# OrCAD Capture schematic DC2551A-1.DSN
size Custom; note: CONFIGURABLE PRECISION AMPLIFIER
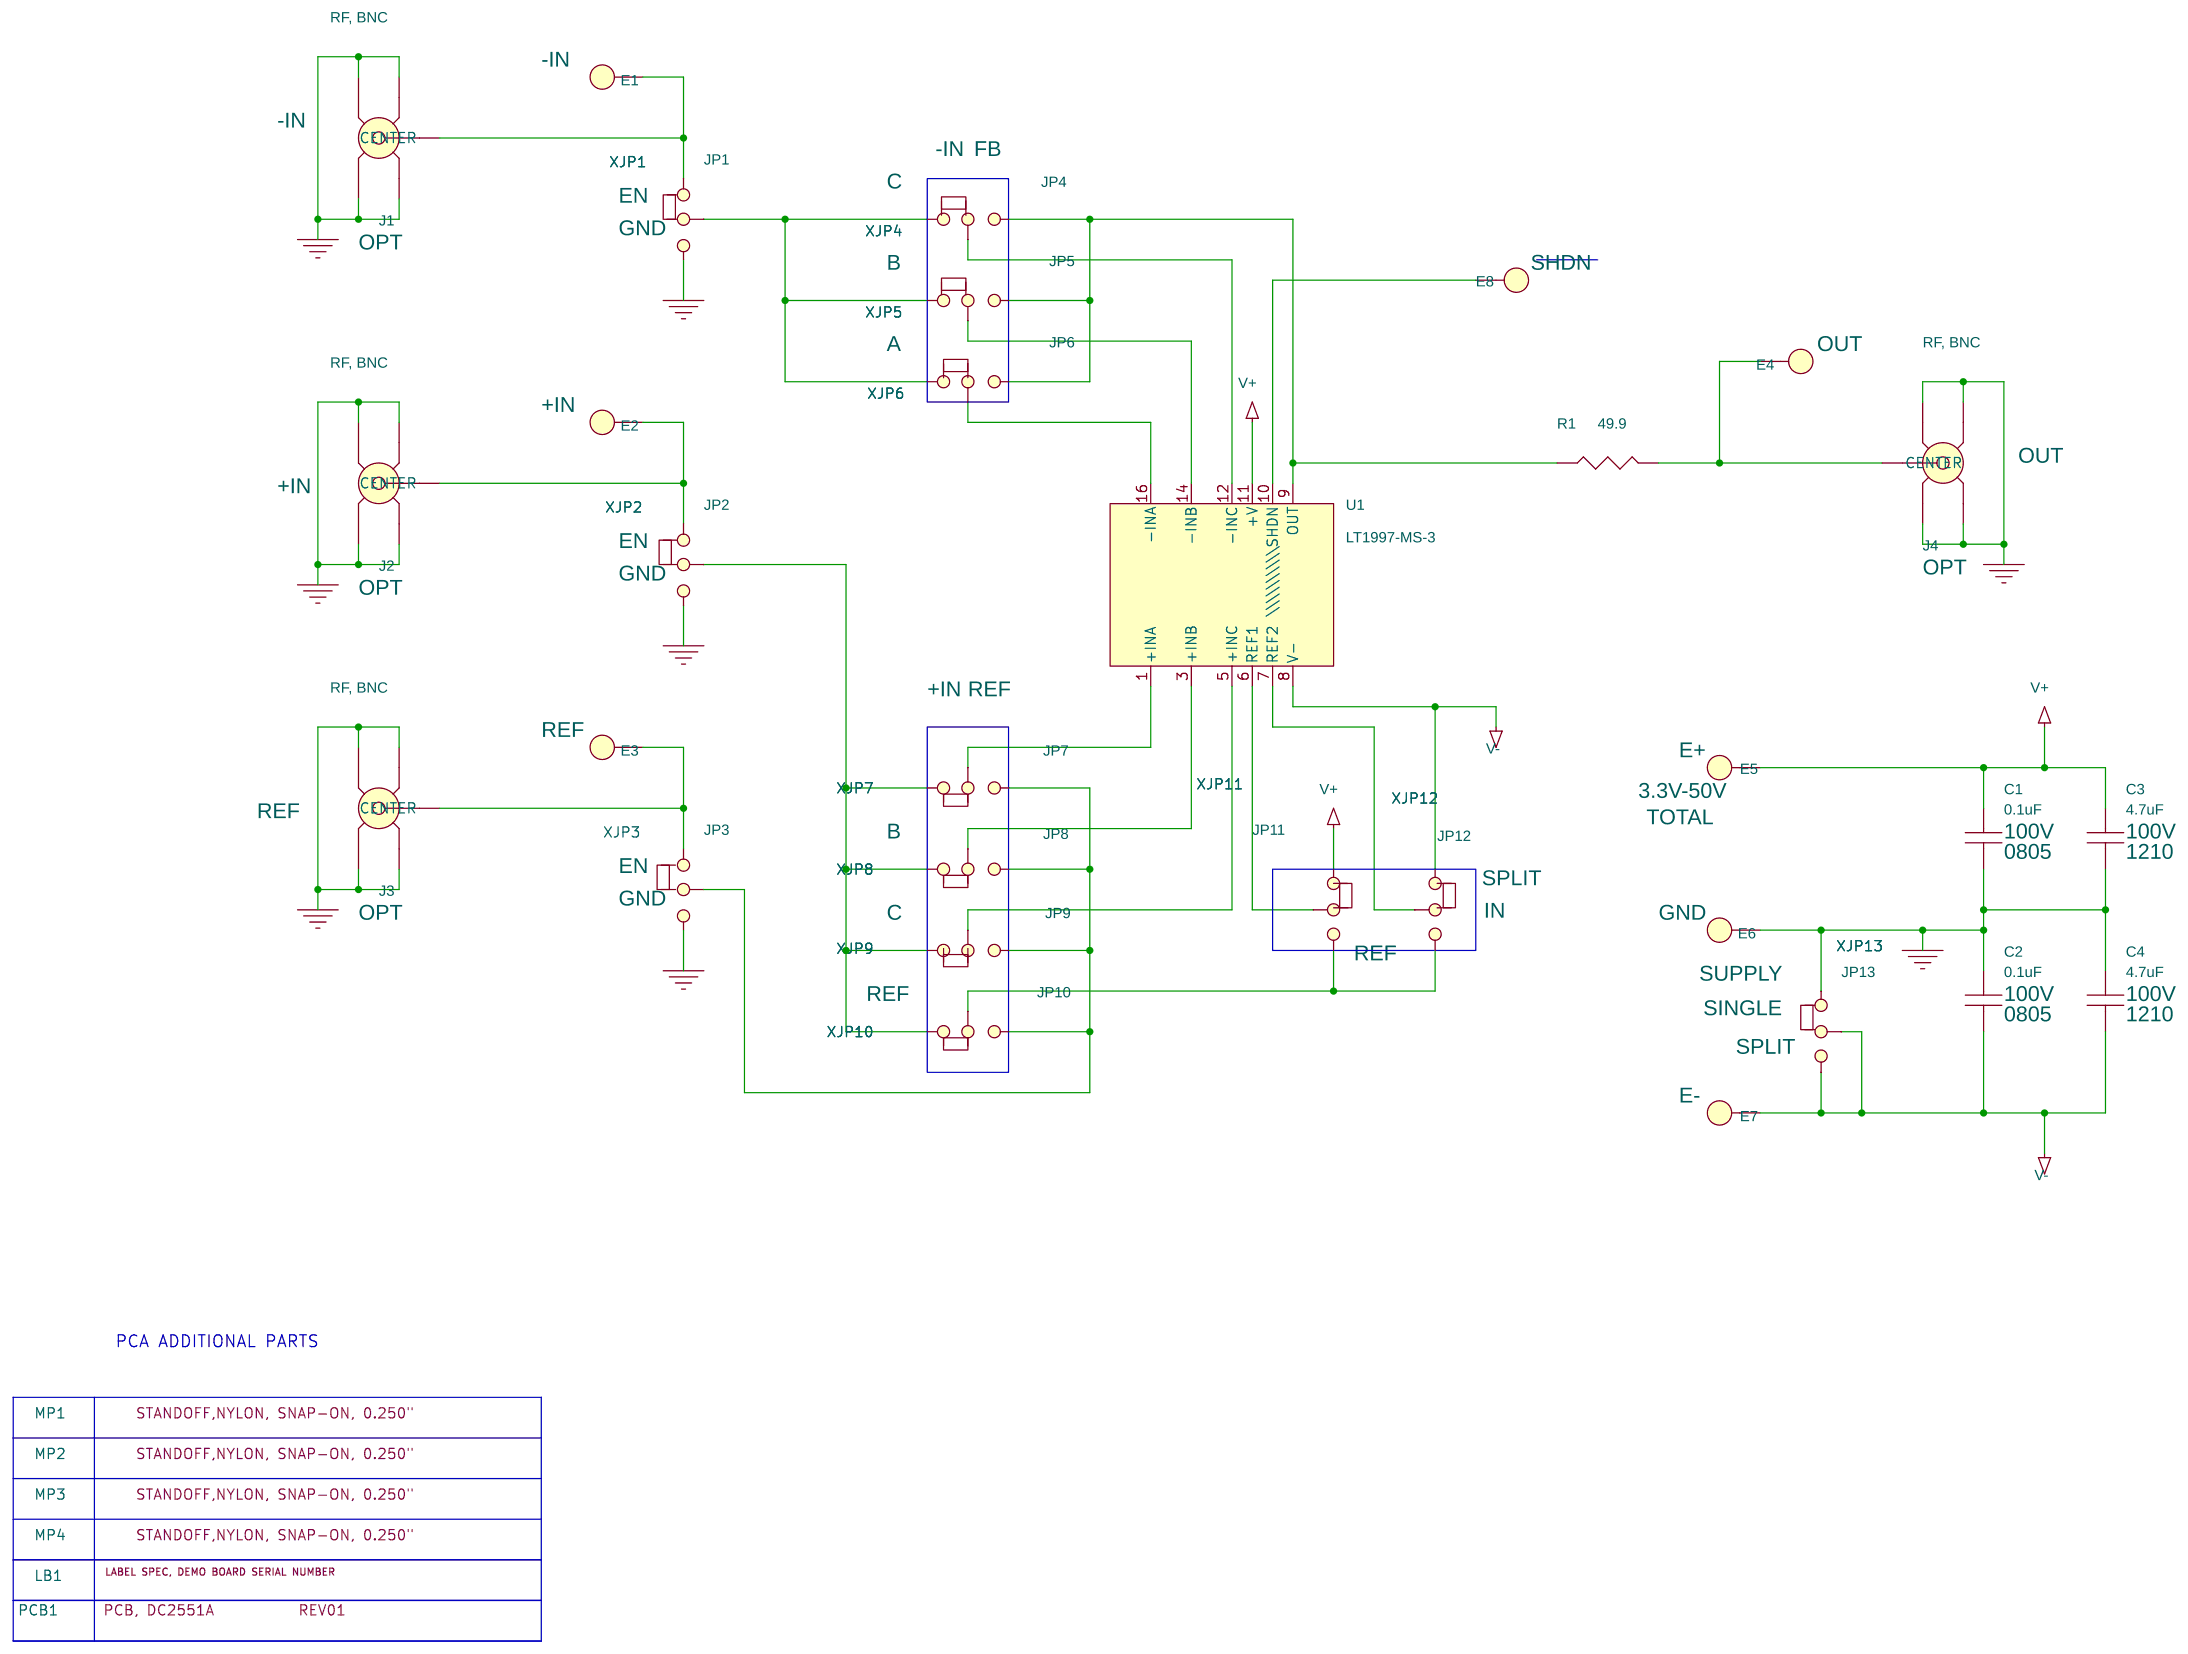
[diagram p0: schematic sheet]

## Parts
C1  0.1uF  [CC0805N]
C2  0.1uF  [CC0805N]
C3  4.7uF  [CC1210N]
C4  4.7uF  [CC1210N]
E1  TEST POINT  [MILLMAX2308]
E2  TEST POINT  [MILLMAX2308]
E3  TEST POINT  [MILLMAX2308]
E4  TEST POINT  [MILLMAX2308]
E5  TEST POINT  [MILLMAX2308]
E6  TEST POINT  [MILLMAX2308]
E7  TEST POINT  [MILLMAX2308]
E8  TEST POINT  [MILLMAX2308]
J1  RF, BNC  [CONNEX-112404]
J2  RF, BNC  [CONNEX-112404]
J3  RF, BNC  [CONNEX-112404]
J4  RF, BNC  [CONNEX-112404]
JP1  HDR.  [HD1X3-079]
JP2  HDR.  [HD1X3-079]
JP3  HDR.  [HD1X3-079]
JP4  HDR.  [HD1X3-079]
JP5  HDR.  [HD1X3-079]
JP6  HDR.  [HD1X3-079]
JP7  HDR.  [HD1X3-079]
JP8  HDR.  [HD1X3-079]
JP9  HDR.  [HD1X3-079]
JP10  HDR.  [HD1X3-079]
JP11  HDR.  [HD1X3-079]
JP12  HDR.  [HD1X3-079]
JP13  HDR.  [HD1X3-079]
LB1  LABEL  [895-0154_REV01]
MP1  STANDOFF  [MTG-8831]
MP2  STANDOFF  [MTG-8831]
MP3  STANDOFF  [MTG-8831]
MP4  STANDOFF  [MTG-8831]
PCB1  PCB, DC2551A
R1  49.9  [CR0402N]
U1  LT1997-MS-3  [LTC-MS-16-1847]
XJP1  SHUNT
XJP2  SHUNT
XJP3  SHUNT
XJP4  SHUNT
XJP5  SHUNT
XJP6  SHUNT
XJP7  SHUNT
XJP8  SHUNT
XJP9  SHUNT
XJP10  SHUNT
XJP11  SHUNT
XJP12  SHUNT
XJP13  SHUNT

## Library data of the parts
C1 C2 = CAP: CAP.,0.1uF,X7R,100V,10%,0805,Automotive; CLASS: DISCRETE; Dielectric Type: X7R; FPLIST: CC0805N,CC0805L,CC0805M; Manufacturer: MURATA; Manufacturer PN: GCM21BR72A104KA37L; PART_NUMBER: 150-3339; Package Size: 0805; Rated Voltage: 100V; Tolerance: 10%; UserField01: Automotive
C3 C4 = CAP: CAP.,4.7uF,X7S,100V,10%,1210,Automotive; CLASS: DISCRETE; Dielectric Type: X7S; FPLIST: CC1210N,CC1210L,CC1210M; Manufacturer: TDK; Manufacturer PN: CGA6M3X7S2A475K200AB; PART_NUMBER: 150-3376; Package Size: 1210; Rated Voltage: 100V; Tolerance: 10%; UserField01: Automotive
E1 = TEST_POINT_.156_MILL-MAX_2308: TEST POINT,TURRET,0.064",MTG. HOLE; 1: -IN; CLASS: IO; Manufacturer: MILL-MAX; Manufacturer PN: 2308-2-00-80-00-00-07-0; PART_NUMBER: 260-0004
E2 = TEST_POINT_.156_MILL-MAX_2308: TEST POINT,TURRET,0.064",MTG. HOLE; 1: +IN; CLASS: IO; Manufacturer: MILL-MAX; Manufacturer PN: 2308-2-00-80-00-00-07-0; PART_NUMBER: 260-0004
E3 = TEST_POINT_.156_MILL-MAX_2308: TEST POINT,TURRET,0.064",MTG. HOLE; 1: REF; CLASS: IO; Manufacturer: MILL-MAX; Manufacturer PN: 2308-2-00-80-00-00-07-0; PART_NUMBER: 260-0004
E4 = TEST_POINT_.156_MILL-MAX_2308: TEST POINT,TURRET,0.064",MTG. HOLE; 1: OUT; CLASS: IO; Manufacturer: MILL-MAX; Manufacturer PN: 2308-2-00-80-00-00-07-0; PART_NUMBER: 260-0004
E5 = TEST_POINT_.156_MILL-MAX_2308: TEST POINT,TURRET,0.064",MTG. HOLE; 1: E+; 2: 3.3V-50V; 3: TOTAL; CLASS: IO; Manufacturer: MILL-MAX; Manufacturer PN: 2308-2-00-80-00-00-07-0; PART_NUMBER: 260-0004
E6 = TEST_POINT_.156_MILL-MAX_2308: TEST POINT,TURRET,0.064",MTG. HOLE; 1: GND; CLASS: IO; Manufacturer: MILL-MAX; Manufacturer PN: 2308-2-00-80-00-00-07-0; PART_NUMBER: 260-0004
E7 = TEST_POINT_.156_MILL-MAX_2308: TEST POINT,TURRET,0.064",MTG. HOLE; 1: E-; CLASS: IO; Manufacturer: MILL-MAX; Manufacturer PN: 2308-2-00-80-00-00-07-0; PART_NUMBER: 260-0004
E8 = TEST_POINT_.156_MILL-MAX_2308: TEST POINT,TURRET,0.064",MTG. HOLE; 1: SHDN; CLASS: IO; Manufacturer: MILL-MAX; Manufacturer PN: 2308-2-00-80-00-00-07-0; PART_NUMBER: 260-0004
J1 = BNC_50_OHM_112404: CONN.,RF, BNC,RCPT,THT, STRT,5-PIN; 1: -IN; BOM Notes: OPT; CLASS: IO; Manufacturer: AMPHENOL CONNEX; Manufacturer PN: 112404; PART_NUMBER: 250-0427
J2 = BNC_50_OHM_112404: CONN.,RF, BNC,RCPT,THT, STRT,5-PIN; 1: +IN; BOM Notes: OPT; CLASS: IO; Manufacturer: AMPHENOL CONNEX; Manufacturer PN: 112404; PART_NUMBER: 250-0427
J3 = BNC_50_OHM_112404: CONN.,RF, BNC,RCPT,THT, STRT,5-PIN; 1: REF; BOM Notes: OPT; CLASS: IO; Manufacturer: AMPHENOL CONNEX; Manufacturer PN: 112404; PART_NUMBER: 250-0427
J4 = BNC_50_OHM_112404: CONN.,RF, BNC,RCPT,THT, STRT,5-PIN; 1: OUT; BOM Notes: OPT; CLASS: IO; Manufacturer: AMPHENOL CONNEX; Manufacturer PN: 112404; PART_NUMBER: 250-0427
JP1-JP3 = 3_PIN_HEADER_.079_SINGLE_ROW: CONN.,HDR.,MALE,1X3,2mm,THT, STRT; 1: EN; 2: GND; CLASS: IO; Manufacturer: SULLINS CONNECTOR SOLUTIONS; Manufacturer PN: NRPN031PAEN-RC; PART_NUMBER: 250-0418
JP4 = 3_PIN_HEADER_.079_SINGLE_ROW: CONN.,HDR.,MALE,1X3,2mm,THT, STRT; 1: -IN; 2: FB; 3: C; CLASS: IO; Manufacturer: SULLINS CONNECTOR SOLUTIONS; Manufacturer PN: NRPN031PAEN-RC; PART_NUMBER: 250-0418
JP5 JP8 = 3_PIN_HEADER_.079_SINGLE_ROW: CONN.,HDR.,MALE,1X3,2mm,THT, STRT; 1: B; CLASS: IO; Manufacturer: SULLINS CONNECTOR SOLUTIONS; Manufacturer PN: NRPN031PAEN-RC; PART_NUMBER: 250-0418
JP6 = 3_PIN_HEADER_.079_SINGLE_ROW: CONN.,HDR.,MALE,1X3,2mm,THT, STRT; 1: A; CLASS: IO; Manufacturer: SULLINS CONNECTOR SOLUTIONS; Manufacturer PN: NRPN031PAEN-RC; PART_NUMBER: 250-0418
JP7 = 3_PIN_HEADER_.079_SINGLE_ROW: CONN.,HDR.,MALE,1X3,2mm,THT, STRT; 1: +IN; 2: REF; CLASS: IO; Manufacturer: SULLINS CONNECTOR SOLUTIONS; Manufacturer PN: NRPN031PAEN-RC; PART_NUMBER: 250-0418
JP9 = 3_PIN_HEADER_.079_SINGLE_ROW: CONN.,HDR.,MALE,1X3,2mm,THT, STRT; 1: C; CLASS: IO; Manufacturer: SULLINS CONNECTOR SOLUTIONS; Manufacturer PN: NRPN031PAEN-RC; PART_NUMBER: 250-0418
JP10 = 3_PIN_HEADER_.079_SINGLE_ROW: CONN.,HDR.,MALE,1X3,2mm,THT, STRT; 1: REF; CLASS: IO; Manufacturer: SULLINS CONNECTOR SOLUTIONS; Manufacturer PN: NRPN031PAEN-RC; PART_NUMBER: 250-0418
JP11 = 3_PIN_HEADER_.079_SINGLE_ROW: CONN.,HDR.,MALE,1X3,2mm,THT, STRT; CLASS: IO; Manufacturer: SULLINS CONNECTOR SOLUTIONS; Manufacturer PN: NRPN031PAEN-RC; PART_NUMBER: 250-0418
JP12 = 3_PIN_HEADER_.079_SINGLE_ROW: CONN.,HDR.,MALE,1X3,2mm,THT, STRT; 1: SPLIT; 2: IN; 3: REF; CLASS: IO; Manufacturer: SULLINS CONNECTOR SOLUTIONS; Manufacturer PN: NRPN031PAEN-RC; PART_NUMBER: 250-0418
JP13 = 3_PIN_HEADER_.079_SINGLE_ROW: CONN.,HDR.,MALE,1X3,2mm,THT, STRT; 1: SINGLE; 2: SPLIT; 3: SUPPLY; CLASS: IO; Manufacturer: SULLINS CONNECTOR SOLUTIONS; Manufacturer PN: NRPN031PAEN-RC; PART_NUMBER: 250-0418
LB1 = BLANK_LABEL: LABEL SPEC, DEMO BOARD SERIAL NUMBER; Manufacturer: BRADY; Manufacturer PN: THT-96-717-10; PART_NUMBER: 895-0154
MP1-MP4 = BLANK_MECHANICAL_PART: STANDOFF,NYLON, SNAP-ON, 0.250"; CLASS: MECHANICAL PART; Manufacturer: KEYSTONE; Manufacturer PN: 8831; PART_NUMBER: 763-0006
PCB1 = BLANK_PCB_PART: BOM Notes: REV01; CLASS: PCB; Manufacturer: GORILLA CIRCUITS; Manufacturer PN: 600-DC2551A; PART_NUMBER: 600-DC2551A
R1 = RES: RES.,49.9 OHMS,1%,1/16W,0402; CLASS: DISCRETE; FPLIST: CR0402N,CR0402L,CR0402M; Manufacturer: NIC; Manufacturer PN: NRC04F49R9TRF; PART_NUMBER: 100-0220; Package Size: 0402; Rated Power: 1/16W; Temperature Coefficient: 100ppm/C; Tolerance: 1%
U1 = LT1997-MS-X: IC,PRECISION WIDE-VOLTAGE AMP,16-pin MSOP; CLASS: IC; Manufacturer: LINEAR TECHNOLOGY; Manufacturer PN: LT1997-3HMS#PBF; PART_NUMBER: LT1997-3HMS#PBF; Package Size: MS16(12); Package Type: 16-pin MSOP
XJP1-XJP13 = SHUNT_2MM_B: CONN.,SHUNT,FEMALE,2 POS,2mm; CLASS: IO; Manufacturer: SAMTEC; Manufacturer PN: 2SN-BK-G; PART_NUMBER: 250-0419

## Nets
GND: C1.2 C2.1 C3.2 C4.1 E6.1(A) J1.2 J1.3 J1.4 J1.5 J2.2 J2.3 J2.4 J2.5 J3.2 J3.3 J3.4 J3.5 J4.2 J4.3 J4.4 J4.5 JP1.3 JP2.3 JP3.3 JP13.3
V+: C1.1 C3.1 E5.1(A) JP11.3 U1.11(+V)
V-: C2.2 C4.2 E7.1(A) JP12.3 JP13.1 JP13.2 U1.8(V-)
N827579: JP4.2 U1.12(-INC)
N827591: JP5.2 U1.14(-INB)
N827603: JP6.2 U1.16(-INA)
N827615: JP7.2 U1.1(+INA)
N827627: JP8.2 U1.3(+INB)
N827639: JP9.2 U1.5(+INC)
N827725: JP4.3 JP5.3 JP6.3 R1.1 U1.9(OUT)
N827775: JP3.2 JP7.3 JP8.3 JP9.3 JP10.3
N827912: E4.1(A) J4.1(CENTER) R1.2
N829245: JP11.2 U1.6(REF1)
N829258: JP12.2 U1.7(REF2)
N829345: JP10.2 JP11.1 JP12.1
N830586: JP1.2 JP4.1 JP5.1 JP6.1
N831354: JP2.2 JP7.1 JP8.1 JP9.1 JP10.1
N831482: E2.1(A) J2.1(CENTER) JP2.1
N832286: E3.1(A) J3.1(CENTER) JP3.1
N842915: E1.1(A) J1.1(CENTER) JP1.1
N845725: E8.1(A) U1.10(\\\\\\\\\\SHDN)

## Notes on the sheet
- PCA ADDITIONAL PARTS
